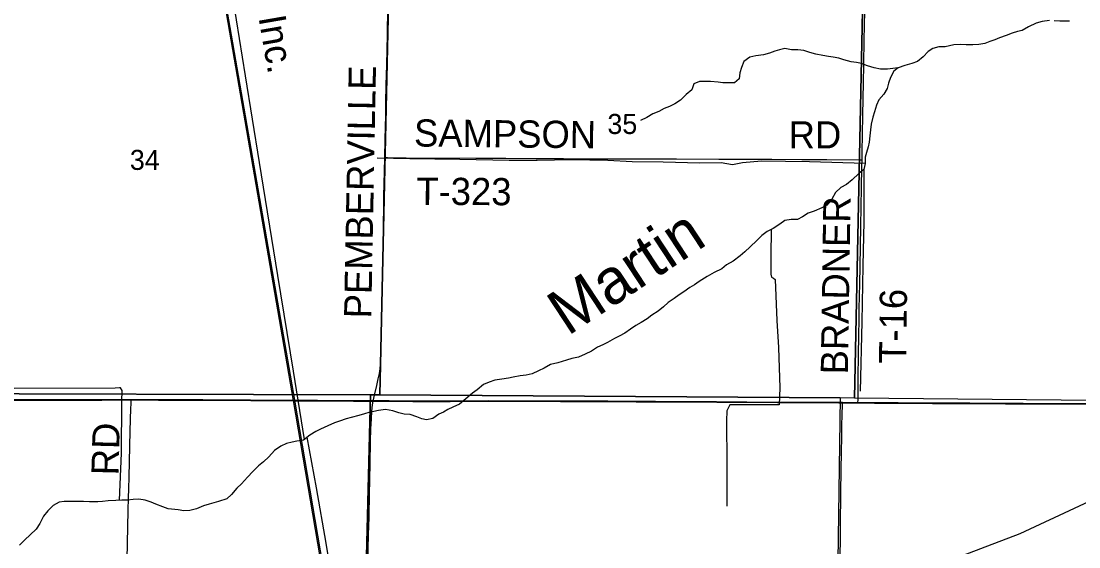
# Model space of a CAD drawing. Extents: x -8.3 to 42.1, y 0 to 22.
# Drawn here: x 5.164 to 7.372, y 18.005 to 19.103 of the extents above; entities that cross this region are included whole.
import ezdxf

# ---------------------------------------------------------------- set-up
doc = ezdxf.new("R2010")
doc.units = 0
for name, color, linetype in [('GM_X_County_Road', 7, 'Continuous'), ('GM_X_County_Road_Text', 7, 'Continuous'), ('GM_X_Minor_River', 7, 'Continuous'), ('GM_X_Minor_River_Text', 7, 'Continuous'), ('GM_X_Rail_Line', 7, 'Continuous'), ('GM_X_Rail_Line_Text', 7, 'Continuous'), ('GM_X_Section', 7, 'Continuous'), ('GM_X_Section_Text', 7, 'Continuous'), ('GM_X_Township_Road', 7, 'Continuous'), ('GM_X_Township_Road_Text', 7, 'Continuous')]:
    doc.layers.add(name, color=color, linetype=linetype)

msp = doc.modelspace()

# ---------------------------------------------------------------- linework, layer by layer
at = {"layer": 'GM_X_County_Road'}
msp.add_line((6.8786, 18.3057), (6.9106, 18.3053), dxfattribs=at)
for points in [[(5.9228, 18.8176), (5.9236, 18.8554), (5.9249, 18.9064), (5.9252, 18.9313), (5.9259, 18.9698), (5.9269, 19.0114), (5.9281, 19.0742), (5.9293, 19.1308), (5.9298, 19.1731), (5.93, 19.1942), (5.9306, 19.2452), (5.9307, 19.308), (5.9308, 19.3255)], [(5.8983, 18.309), (5.901, 18.3218), (5.9059, 18.3419), (5.9092, 18.3559), (5.9114, 18.3669), (5.9128, 18.3762), (5.9139, 18.3855), (5.9145, 18.3967), (5.915, 18.416), (5.9161, 18.4669), (5.9166, 18.5011), (5.9197, 18.654), (5.921, 18.7373), (5.9221, 18.7889), (5.9228, 18.8176)], [(4.9123, 18.3127), (4.9217, 18.3127), (5.0025, 18.3122), (5.046, 18.3119), (5.13, 18.3112), (5.1921, 18.3111), (5.2356, 18.311), (5.332, 18.3111), (5.3724, 18.3114), (5.3933, 18.3114)], [(5.3933, 18.3114), (5.4035, 18.3115), (5.4501, 18.3113), (5.5247, 18.311), (5.5433, 18.3108), (5.5806, 18.3108), (5.6428, 18.3105), (5.6832, 18.3102), (5.705, 18.3101), (5.7267, 18.3101), (5.736, 18.31), (5.764, 18.3098), (5.7826, 18.3097), (5.8572, 18.3093), (5.8983, 18.309)], [(5.8868, 17.9445), (5.889, 18.0297), (5.8898, 18.0657), (5.8898, 18.0702), (5.8908, 18.1139), (5.8914, 18.1452), (5.8922, 18.1794), (5.8927, 18.2245), (5.8933, 18.2509), (5.8947, 18.2724), (5.8958, 18.288), (5.8971, 18.3014), (5.8983, 18.309)], [(5.8983, 18.309), (5.9007, 18.309), (5.9318, 18.3089), (5.9815, 18.3086), (6.0592, 18.3086), (6.0996, 18.3087), (6.1401, 18.3089), (6.2333, 18.3087), (6.2892, 18.3082), (6.3328, 18.3084), (6.3887, 18.3084), (6.4477, 18.3075), (6.4882, 18.3075), (6.6156, 18.3069), (6.743, 18.3059), (6.7834, 18.3059), (6.8705, 18.3058), (6.8786, 18.3057)], [(6.9106, 18.3053), (6.945, 18.3048), (6.9948, 18.3048), (7.029, 18.3045), (7.0663, 18.3044), (7.0911, 18.3043), (7.144, 18.3041), (7.2186, 18.3036), (7.2559, 18.3034), (7.3398, 18.3031), (7.4424, 18.3029), (7.5045, 18.3023), (7.5605, 18.3019), (7.6413, 18.3016), (7.6879, 18.3013), (7.7998, 18.3003), (7.8682, 18.3), (7.9024, 18.2999), (7.9119, 18.2999)]]:
    msp.add_lwpolyline(points, dxfattribs=at)
at = {"layer": 'GM_X_Minor_River'}
for points in [[(5.755, 18.2292), (5.7321, 18.3713), (5.6995, 18.5714), (5.6614, 18.8072), (5.6319, 18.9882), (5.6066, 19.144), (5.5933, 19.2339), (5.5787, 19.3184), (5.5544, 19.4826)], [(7.3101, 19.1042), (7.2953, 19.1019), (7.2823, 19.0984), (7.2666, 19.0908), (7.2535, 19.0832), (7.2433, 19.0812), (7.2326, 19.0776), (7.2196, 19.0726), (7.2062, 19.0676), (7.1962, 19.0637), (7.1859, 19.0602), (7.1756, 19.0562), (7.1627, 19.0539), (7.1502, 19.0531), (7.1365, 19.0534), (7.1248, 19.0541), (7.1104, 19.0529), (7.0925, 19.0491), (7.0796, 19.0487), (7.0666, 19.0452), (7.057, 19.039), (7.0469, 19.0279), (7.0349, 19.0183), (7.0231, 19.014), (7.0086, 19.0102), (6.9948, 19.0052), (6.9852, 18.9982), (6.9788, 18.9847), (6.9743, 18.9727), (6.9714, 18.9618)], [(7.3525, 19.1028), (7.3419, 19.1023), (7.332, 19.1025), (7.3203, 19.1032)], [(6.9948, 19.0052), (6.972, 19.002), (6.9573, 19.0023), (6.9441, 19.0049), (6.9306, 19.0091), (6.9182, 19.0143), (6.9073, 19.0161), (6.8967, 19.0178), (6.8809, 19.022), (6.8704, 19.0249), (6.8591, 19.0275), (6.8489, 19.0289), (6.8372, 19.031), (6.8225, 19.0337), (6.8101, 19.037), (6.7977, 19.0415), (6.7852, 19.0429), (6.772, 19.0429), (6.758, 19.0451), (6.7466, 19.0427), (6.7371, 19.0399), (6.7256, 19.036), (6.7134, 19.0325), (6.697, 19.0303), (6.6845, 19.0272), (6.6721, 19.0184), (6.6677, 19.0059), (6.664, 18.9946), (6.6625, 18.9822), (6.6525, 18.974), (6.6415, 18.9736), (6.6282, 18.9735), (6.6184, 18.9749), (6.6026, 18.9768), (6.5908, 18.9767), (6.5798, 18.9762), (6.5676, 18.9716), (6.5639, 18.9591), (6.5519, 18.9492), (6.5399, 18.9377), (6.5279, 18.9296), (6.5168, 18.9246), (6.5061, 18.9199), (6.495, 18.9137), (6.4823, 18.9087), (6.4697, 18.9014), (6.4566, 18.8949)], [(6.9714, 18.9618), (6.9647, 18.9498), (6.9538, 18.9379), (6.9494, 18.9274), (6.9452, 18.9134), (6.9419, 18.9018), (6.9381, 18.8874), (6.9367, 18.8757), (6.9356, 18.8632), (6.9338, 18.85), (6.9317, 18.8402), (6.9283, 18.8281), (6.9254, 18.8183), (6.9255, 18.805), (6.9225, 18.7926), (6.9125, 18.7841), (6.8981, 18.7711), (6.8865, 18.7612), (6.8746, 18.755), (6.8638, 18.745), (6.8562, 18.7308), (6.8453, 18.7182), (6.835, 18.7127), (6.8193, 18.7055), (6.8063, 18.7013), (6.7951, 18.6939), (6.7844, 18.6885), (6.7711, 18.6881), (6.7578, 18.6865), (6.7474, 18.6784), (6.7335, 18.6692), (6.7209, 18.6635), (6.7101, 18.6546), (6.6992, 18.6447), (6.6856, 18.6313), (6.6744, 18.621), (6.6643, 18.6125), (6.65, 18.6014), (6.6362, 18.5934), (6.6265, 18.5853), (6.6105, 18.5777), (6.5959, 18.5694), (6.5793, 18.5591), (6.5693, 18.5522), (6.5597, 18.546), (6.547, 18.5375), (6.537, 18.5309), (6.5269, 18.5236), (6.5146, 18.5152), (6.5045, 18.5063), (6.4937, 18.4967), (6.4799, 18.4883), (6.4702, 18.481), (6.4579, 18.4733), (6.4468, 18.4671), (6.436, 18.459), (6.4236, 18.4513), (6.4121, 18.4448), (6.4022, 18.4397), (6.3876, 18.4313), (6.378, 18.4266), (6.3669, 18.422), (6.3542, 18.4132), (6.3411, 18.407), (6.327, 18.4009), (6.3129, 18.3982), (6.3022, 18.3943), (6.2839, 18.3891), (6.269, 18.3853), (6.2556, 18.378), (6.2437, 18.3726), (6.2307, 18.3657), (6.2181, 18.3634), (6.2056, 18.3618), (6.1907, 18.3591), (6.1808, 18.357), (6.1672, 18.3551), (6.1527, 18.3528), (6.1405, 18.3489), (6.129, 18.3439), (6.1155, 18.3324), (6.1058, 18.3258), (6.0919, 18.3137), (6.0784, 18.303), (6.065, 18.2961), (6.0546, 18.2914), (6.045, 18.2863), (6.0354, 18.2816), (6.0231, 18.2728), (6.0101, 18.2697), (6, 18.2719), (5.9895, 18.2763), (5.976, 18.2808), (5.9635, 18.2815), (5.9522, 18.2848), (5.9398, 18.2889), (5.9243, 18.2915), (5.9099, 18.2896), (5.8996, 18.2876), (5.8897, 18.2855), (5.8802, 18.2824)], [(6.9255, 18.805), (6.8097, 18.809), (6.709, 18.8099), (6.6692, 18.8067), (6.6486, 18.8022), (6.6248, 18.8066), (6.5801, 18.8062), (6.5037, 18.8084), (6.4389, 18.8085), (6.3883, 18.8112), (6.313, 18.813), (6.241, 18.8117), (6.1823, 18.8116), (6.0797, 18.8137), (5.9748, 18.8148), (5.9067, 18.8164)], [(6.9225, 18.7926), (6.9226, 18.7337), (6.9229, 18.684), (6.9209, 18.5915), (6.9188, 18.4743), (6.9152, 18.3297)], [(6.729, 18.6672), (6.7287, 18.6124), (6.7289, 18.5741), (6.7303, 18.568), (6.734, 18.566), (6.7377, 18.5629), (6.7413, 18.4774), (6.7448, 18.4208), (6.7476, 18.3368), (6.746, 18.3016), (6.6702, 18.3015), (6.6433, 18.301), (6.6366, 18.2887), (6.6361, 18.2678), (6.6365, 18.1786), (6.637, 18.0894)], [(5.3686, 18.1021), (5.373, 18.2005), (5.3738, 18.3083), (5.3747, 18.3314), (5.3707, 18.3368), (5.3688, 18.3369), (5.3601, 18.3359), (5.1491, 18.3357), (4.9564, 18.3374), (4.7921, 18.3395), (4.6259, 18.3401), (4.5126, 18.3379), (4.3993, 18.338), (4.2857, 18.3373), (4.1695, 18.3378), (4.0142, 18.3374)], [(5.8802, 18.2824), (5.8684, 18.2789), (5.8527, 18.2751), (5.8424, 18.2723), (5.8283, 18.2669), (5.818, 18.2634), (5.8035, 18.2577), (5.7885, 18.2508), (5.7785, 18.2457), (5.7659, 18.2381), (5.7527, 18.2274), (5.739, 18.2251), (5.7291, 18.223), (5.7177, 18.2206), (5.7055, 18.2149), (5.6923, 18.2057), (5.6807, 18.1927), (5.6694, 18.1823), (5.6594, 18.1742), (5.647, 18.162), (5.6361, 18.1501), (5.6236, 18.1364), (5.6139, 18.1275), (5.603, 18.1138), (5.5929, 18.1053), (5.5757, 18.0992), (5.5563, 18.0936), (5.5441, 18.0901), (5.5295, 18.0844), (5.5158, 18.0809), (5.5029, 18.0801), (5.4916, 18.0823), (5.4705, 18.0843), (5.4592, 18.0884), (5.4449, 18.0937), (5.4352, 18.0981), (5.4224, 18.1022), (5.4092, 18.104), (5.3975, 18.1039), (5.3853, 18.1023), (5.3736, 18.1022), (5.3611, 18.1018), (5.3451, 18.1006), (5.3337, 18.0994), (5.3235, 18.0989), (5.3061, 18.0986), (5.2936, 18.0992), (5.2811, 18.0992), (5.2678, 18.0991), (5.2534, 18.0991), (5.2432, 18.0982), (5.2301, 18.0913), (5.2196, 18.0802), (5.2099, 18.069), (5.2023, 18.0533), (5.1952, 18.042), (5.1824, 18.0298), (5.1716, 18.0191), (5.1603, 18.0083)], [(5.7602, 18.2335), (5.7798, 18.1277), (5.7996, 18.0122), (5.821, 17.88)]]:
    msp.add_lwpolyline(points, dxfattribs=at)
at = {"layer": 'GM_X_Rail_Line'}
for points in [[(5.9654, 16.7643), (5.9567, 16.8335), (5.932, 17.0379), (5.9087, 17.2246), (5.8981, 17.3081), (5.8822, 17.4435), (5.8389, 17.6857), (5.7322, 18.3104), (5.5565, 19.3262), (5.427, 20.0822), (5.2858, 20.9)], [(6.2899, 14.1), (6.2222, 14.6512), (6.0176, 16.3351), (5.9781, 16.679), (5.9602, 16.8313), (5.9345, 17.0381), (5.9111, 17.2249), (5.9006, 17.3084), (5.8846, 17.4439), (5.8413, 17.6862), (5.7347, 18.3108), (5.559, 19.3267), (5.4294, 20.0826), (5.2883, 20.9)], [(5.9044, 17.3082), (6.0693, 17.3942), (6.218, 17.4628), (6.6389, 17.7213), (6.9437, 17.9671), (7.085, 17.9703), (7.2495, 18.0325), (7.9103, 18.3409)]]:
    msp.add_lwpolyline(points, dxfattribs=at)
at = {"layer": 'GM_X_Section'}
for points in [[(5.9346, 19.331), (5.9121, 18.3219), (5.8932, 18.3221), (4.9147, 18.3251), (4.9315, 19.3303)], [(6.9241, 19.3275), (6.9034, 18.3155), (6.8731, 18.3158), (5.9121, 18.3219), (5.9346, 19.331)], [(7.9268, 19.313), (7.9258, 19.2592), (7.9095, 18.3054), (6.9034, 18.3155), (6.9241, 19.3275)], [(4.9147, 18.3251), (5.8932, 18.3221), (5.8682, 17.3386), (5.431, 17.3522), (4.866, 17.3546), (4.8893, 18.3249)], [(5.9121, 18.3219), (6.8731, 18.3158), (6.8593, 17.3438), (5.8682, 17.3386), (5.8932, 18.3221)]]:
    msp.add_lwpolyline(points, close=True, dxfattribs=at)
at = {"layer": 'GM_X_Township_Road'}
msp.add_line((6.8786, 18.3057), (6.9106, 18.3053), dxfattribs=at)
for points in [[(6.919, 18.8131), (6.9192, 18.8299), (6.9198, 18.8657), (6.9206, 18.9061), (6.922, 18.9745), (6.9231, 19.0103), (6.9238, 19.0647), (6.9243, 19.0911), (6.9245, 19.102), (6.9246, 19.1144), (6.925, 19.1424), (6.9251, 19.1564), (6.9253, 19.172), (6.9259, 19.2031), (6.9265, 19.2342), (6.927, 19.2606), (6.928, 19.3134), (6.928, 19.3188)], [(5.9228, 18.8176), (5.9282, 18.8176), (5.9674, 18.8174), (6.1128, 18.8165), (6.1489, 18.8165), (6.1756, 18.8165), (6.2384, 18.8158), (6.2956, 18.8155), (6.3298, 18.8153), (6.3627, 18.8151), (6.4025, 18.8149), (6.4186, 18.8149)], [(6.4186, 18.8149), (6.4479, 18.815), (6.5318, 18.8148), (6.6201, 18.8146), (6.6692, 18.8145), (6.7307, 18.8141), (6.7935, 18.8138), (6.8457, 18.8135), (6.9128, 18.8131), (6.919, 18.8131)], [(6.9106, 18.3053), (6.9107, 18.3122), (6.911, 18.3557), (6.9119, 18.4086), (6.9124, 18.4428), (6.9131, 18.4832), (6.9134, 18.5019), (6.9143, 18.5547), (6.9149, 18.5905), (6.9163, 18.6745), (6.9179, 18.7553), (6.9187, 18.7973), (6.919, 18.8131)], [(7.4421, 18.3034), (7.3396, 18.3036), (7.2556, 18.304), (7.2183, 18.3041), (7.1438, 18.3047), (7.0909, 18.3048), (7.0661, 18.3049), (7.0287, 18.3051), (6.9946, 18.3053), (6.9448, 18.3054), (6.9104, 18.3058), (6.8784, 18.3062), (6.8702, 18.3063), (6.7832, 18.3064), (6.7428, 18.3064), (6.6154, 18.3075), (6.4879, 18.308), (6.4475, 18.3081), (6.3885, 18.309), (6.3325, 18.309), (6.289, 18.3088), (6.2331, 18.3093), (6.1398, 18.3095), (6.0994, 18.3093), (6.059, 18.3092), (5.9813, 18.3092), (5.9316, 18.3095), (5.9005, 18.3096), (5.8981, 18.3095), (5.857, 18.3099), (5.7824, 18.3103), (5.7637, 18.3104), (5.7358, 18.3106), (5.7265, 18.3106), (5.7047, 18.3106), (5.683, 18.3107), (5.6426, 18.3111), (5.5804, 18.3113), (5.5431, 18.3114), (5.5245, 18.3116), (5.4499, 18.3119), (5.4033, 18.312), (5.393, 18.312), (5.3722, 18.312), (5.3318, 18.3117), (5.2354, 18.3116), (5.1919, 18.3117), (5.1297, 18.3118)], [(5.1297, 18.3118), (5.1919, 18.3117), (5.2354, 18.3116), (5.3318, 18.3117), (5.3722, 18.312), (5.393, 18.312), (5.4033, 18.312), (5.4499, 18.3119), (5.5245, 18.3116), (5.5431, 18.3114), (5.5804, 18.3113), (5.6426, 18.3111), (5.683, 18.3107), (5.7047, 18.3106), (5.7265, 18.3106), (5.7358, 18.3106), (5.7637, 18.3104), (5.7824, 18.3103), (5.857, 18.3099), (5.8981, 18.3095), (5.9005, 18.3096), (5.9316, 18.3095), (5.9813, 18.3092), (6.059, 18.3092), (6.0994, 18.3093), (6.1398, 18.3095), (6.2331, 18.3093), (6.289, 18.3088), (6.3325, 18.309), (6.3885, 18.309), (6.4475, 18.3081), (6.4879, 18.308), (6.6154, 18.3075), (6.7428, 18.3064), (6.7832, 18.3064), (6.8702, 18.3063), (6.8784, 18.3062), (6.9104, 18.3058), (6.9448, 18.3054), (6.9946, 18.3053), (7.0287, 18.3051), (7.0661, 18.3049), (7.0909, 18.3048), (7.1438, 18.3047), (7.2183, 18.3041), (7.2556, 18.304), (7.3396, 18.3036), (7.4421, 18.3034)], [(5.3735, 17.4736), (5.3737, 17.4871), (5.3742, 17.5136), (5.375, 17.5384), (5.3764, 17.599), (5.3775, 17.6503), (5.3784, 17.6845), (5.3797, 17.7436), (5.3803, 17.7731), (5.3809, 17.812), (5.3825, 17.885), (5.3836, 17.9379), (5.3846, 17.9783), (5.3854, 18.0125), (5.3871, 18.0809), (5.3876, 18.1073), (5.3881, 18.126), (5.389, 18.1508), (5.3903, 18.2146), (5.3912, 18.2472), (5.3926, 18.2938), (5.393, 18.3032), (5.3933, 18.3114)], [(6.8715, 17.7285), (6.8719, 17.7424), (6.8719, 17.7641), (6.8719, 17.7968), (6.8722, 17.8512), (6.8728, 17.9071), (6.8734, 17.96), (6.8743, 18.047), (6.8751, 18.1201), (6.8762, 18.2055), (6.8767, 18.232), (6.8771, 18.2568), (6.8776, 18.2817), (6.8784, 18.3004), (6.8786, 18.3057)]]:
    msp.add_lwpolyline(points, dxfattribs=at)

# ---------------------------------------------------------------- texts
at = {"layer": 'GM_X_County_Road_Text'}
msp.add_text('PEMBERVILLE', height=0.056818, rotation=88.9085, dxfattribs=at).set_placement((5.8944, 18.4815))
at = {"layer": 'GM_X_Minor_River_Text'}
msp.add_text('Martin', height=0.09475, rotation=33.3118, dxfattribs=at).set_placement((6.3045, 18.444))
at = {"layer": 'GM_X_Rail_Line_Text'}
msp.add_text('Inc.', height=0.05663, rotation=279.7937, dxfattribs=at).set_placement((5.6589, 19.1104))
at = {"layer": 'GM_X_Section_Text'}
for s, p in [('35', (6.3875, 18.8669)), ('34', (5.3905, 18.7919))]:
    msp.add_text(s, height=0.04186, rotation=0, dxfattribs=at).set_placement(p)
at = {"layer": 'GM_X_Township_Road_Text'}
for s, rotation, p in [('SAMPSON', 359.4194, (5.9836, 18.8408)), ('RD', 0, (6.7659, 18.8367)), ('T-323', 359.7178, (5.9886, 18.719)), ('BRADNER', 89.1385, (6.8896, 18.3646)), ('T-16', 89.3118, (7.0112, 18.3869)), ('RD', 88.5174, (5.3669, 18.1536))]:
    msp.add_text(s, height=0.05682, rotation=rotation, dxfattribs=at).set_placement(p)

doc.saveas('drawing.dxf')
